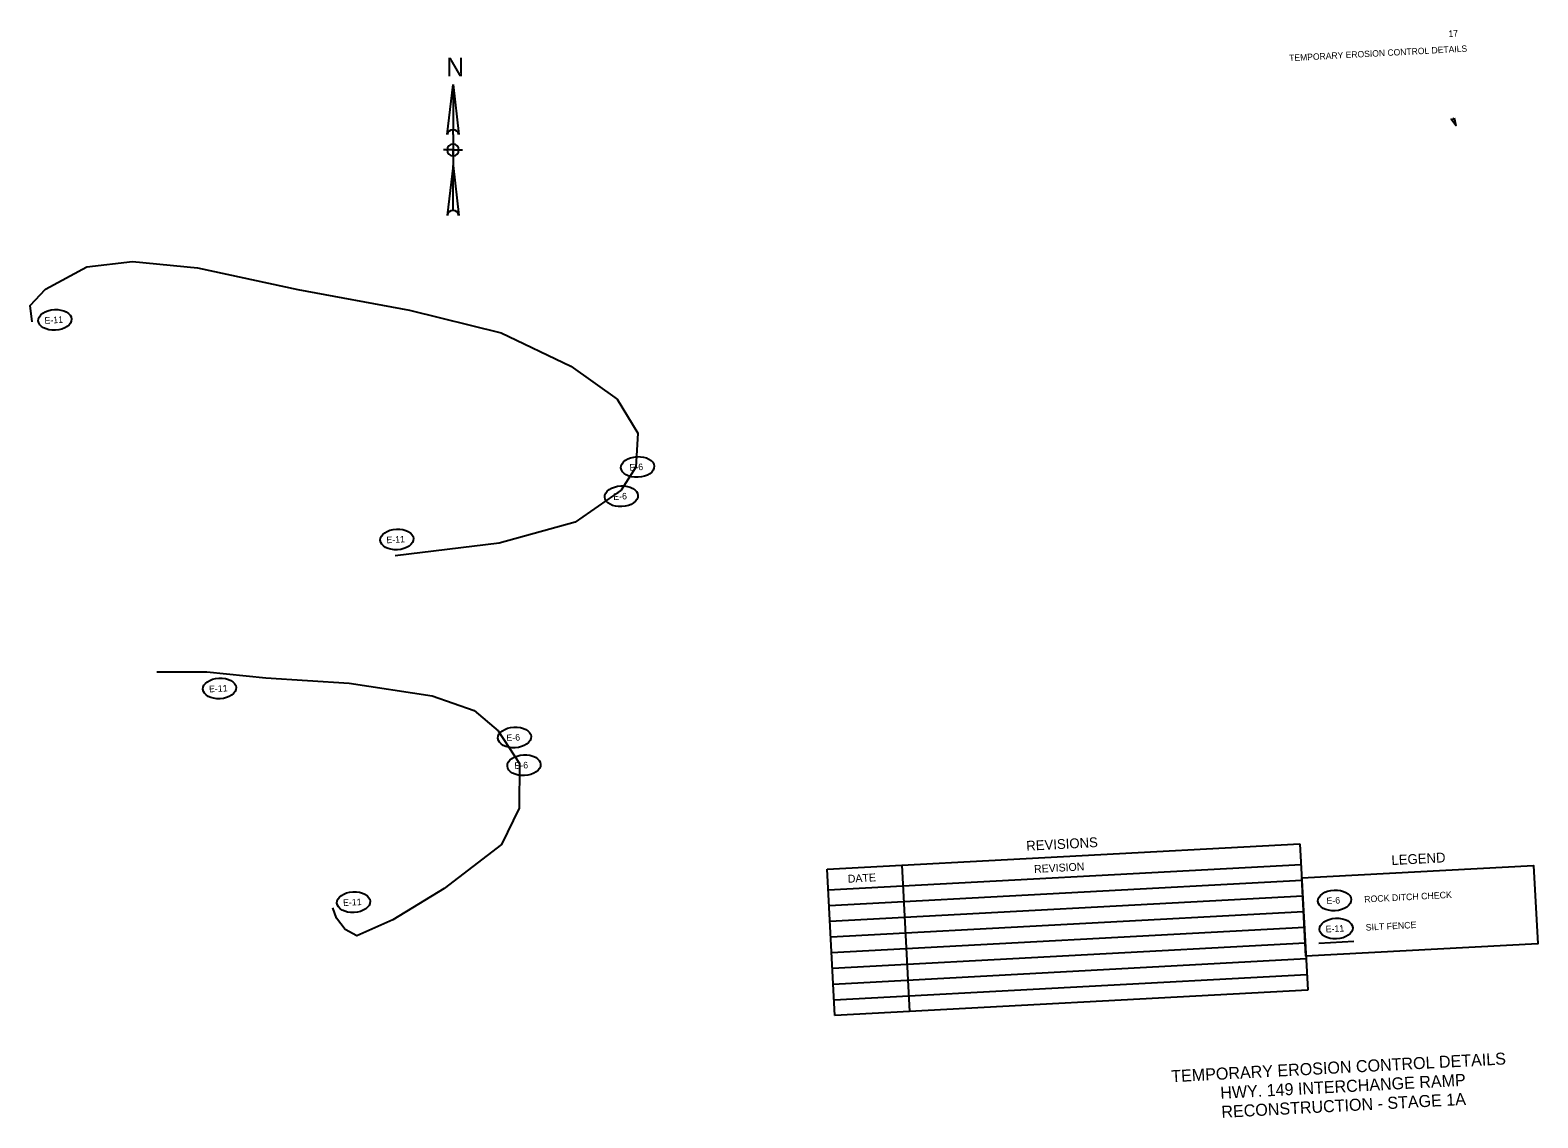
# Model space of a CAD drawing. Extents: x 251493 to 254667, y 216764 to 225410.
# Drawn here: x 251493 to 254251, y 223420 to 225410 of the extents above; entities that cross this region are included whole.
import ezdxf

# ---------------------------------------------------------------- set-up
doc = ezdxf.new("R2010")
doc.units = 0
for name, color, linetype in [('24X36', 7, 'Continuous'), ('Level 1', 7, 'Continuous'), ('Level 2', 7, 'Continuous'), ('Level 30', 7, 'Continuous'), ('Level 58', 7, 'Continuous')]:
    doc.layers.add(name, color=color, linetype=linetype)

msp = doc.modelspace()

# ---------------------------------------------------------------- linework, layer by layer
at = {"layer": '24X36'}
msp.add_line((253850.8, 223739.5), (253914.7, 223743), dxfattribs=at)
for points in [[(251496.9, 224876.5), (251493, 224906.2), (251521.2, 224936.4), (251596.8, 224977.5), (251680, 224986.8), (251799, 224975.2), (251982.9, 224936), (252187.1, 224897.9), (252354.4, 224856.6), (252482, 224795.3), (252566.6, 224735.2), (252604.6, 224672.7), (252600.8, 224610.3), (252574.3, 224568.2), (252490.2, 224509.9), (252351.1, 224471.3), (252161, 224448)], [(251725, 224235.7), (251815.9, 224235.7), (251924.2, 224224.8), (252076.6, 224215), (252228.5, 224192.1), (252305.3, 224165.1), (252349.2, 224128), (252388.3, 224067.9), (252387.8, 223986.5), (252355.5, 223920.2), (252250.4, 223839.2), (252156.6, 223782.2), (252090.6, 223752.9), (252069, 223764.3), (252053.6, 223785), (252046.6, 223803.8)]]:
    msp.add_lwpolyline(points, dxfattribs=at)
at = {"layer": 'Level 1'}
for p, q in [((252255.7, 225219.4), (252266.6, 225310.9)), ((252266.6, 225310.9), (252277.5, 225219.4)), ((252266.6, 225310.9), (252266.6, 225228.1)), ((252266.6, 225219.4), (252266.6, 225228.1)), ((252266.6, 225219.4), (252266.6, 225202)), ((252255.3, 225191.1), (252249.2, 225191.1)), ((252266.6, 225191.1), (252256.1, 225191.1)), ((252266.6, 225202), (252266.6, 225191.1)), ((252266.6, 225191.1), (252266.6, 225180.2)), ((252266.6, 225191.1), (252277.5, 225191.1)), ((252266.6, 225180.2), (252266.6, 225191.1)), ((252277.5, 225191.1), (252284.1, 225191.1)), ((252277.5, 225191.1), (252277.5, 225191.1)), ((252266.6, 225162.8), (252255.7, 225071.4)), ((252266.6, 225180.2), (252266.6, 225162.8)), ((252266.6, 225080.1), (252266.6, 225162.8)), ((252266.6, 225162.8), (252277.5, 225071.4)), ((252951.1, 223874.6), (253816.1, 223920.9)), ((253816.1, 223920.9), (253830.4, 223653.5)), ((252965.4, 223607.1), (252951.1, 223874.6)), ((252953.1, 223837.2), (253818.1, 223883.5)), ((253087.5, 223881.9), (253101.8, 223614.4)), ((252954.6, 223808.4), (253819.6, 223854.8)), ((252956.2, 223779.7), (253821.2, 223826)), ((252957.7, 223750.9), (253822.7, 223797.2)), ((252959.2, 223722.1), (253824.2, 223768.5)), ((252960.8, 223693.4), (253825.8, 223739.7)), ((252962.3, 223664.6), (253827.3, 223711)), ((252963.9, 223635.9), (253828.9, 223682.2)), ((253830.4, 223653.5), (252965.4, 223607.1)), ((253830.4, 223653.5), (253830.4, 223653.5))]:
    msp.add_line(p, q, dxfattribs=at)
msp.add_lwpolyline([(253819.4, 223859.1), (254243.6, 223881.8), (254251.3, 223738), (253827.1, 223715.3)], close=True, dxfattribs=at)
for centre, radius, start, end in [((252266.6, 225217), 11.2, 90, 167.3196), ((252266.6, 225217), 11.2, 12.6804, 90), ((252266.6, 225191.1), 10.9, 90, 180), ((252266.6, 225191.1), 10.9, 180, 270), ((252266.6, 225191.1), 10.9, 0, 90), ((252266.6, 225191.1), 10.9, 270, 0), ((252266.6, 225068.9), 11.2, 90, 167.3196), ((252266.6, 225068.9), 11.2, 12.6804, 90)]:
    msp.add_arc(centre, radius, start, end, dxfattribs=at)
at = {"layer": 'Level 30'}
for centre in [(251538.3, 224880.1), (252604.3, 224610.9), (252574.6, 224557.3), (252163.9, 224478.3), (251839.4, 224205.6), (252379.1, 224115.9), (252396.5, 224065.1), (253879.4, 223817.6), (252084.6, 223814.4), (253882.2, 223766.1)]:
    msp.add_ellipse(centre, major_axis=(30.4, 1.6), ratio=0.622507, dxfattribs=at)
at = {"layer": 'Level 58'}
msp.add_lwpolyline([(254097.9, 225250.1), (254101.1, 225235.7), (254092.5, 225247.6), (254096.2, 225246.7)], close=True, dxfattribs=at)

# ---------------------------------------------------------------- texts
at = {"layer": 'Level 1'}
for s, height, p in [('17', 11.72, (254088, 225397.9)), ('TEMPORARY EROSION CONTROL DETAILS', 11.7, (253796.7, 225353.6)), ('DATE', 14.4, (252989.2, 223849.9)), ('REVISION', 14.4, (253330, 223867.8))]:
    msp.add_text(s, height=height, rotation=3.0666, dxfattribs=at).set_placement(p)
msp.add_text('N', height=34.2, dxfattribs=at).set_placement((252254, 225325.9))
at = {"layer": 'Level 2'}
for s, p in [('TEMPORARY EROSION CONTROL DETAILS', (253581.2, 223484.7)), ('HWY. 149 INTERCHANGE RAMP', (253670.9, 223454.4)), ('RECONSTRUCTION - STAGE 1A', (253672.9, 223419.5))]:
    msp.add_text(s, height=22, rotation=3.0666, dxfattribs=at).set_placement(p)
at = {"layer": 'Level 30'}
for s, height, p in [('E-11', 12, (251519.5, 224873)), ('E-6', 12, (252589.8, 224604)), ('E-6', 12, (252560.1, 224550.4)), ('E-11', 12, (252145.1, 224471.2)), ('E-11', 12, (251820.6, 224198.4)), ('E-6', 12, (252364.6, 224109)), ('E-6', 12, (252379.3, 224058.1)), ('REVISIONS', 18, (253315.8, 223908.4)), ('LEGEND', 18, (253983.9, 223882.2)), ('E-11', 12, (252065.8, 223807.3)), ('E-6', 12, (253864.9, 223810.7)), ('ROCK DITCH CHECK', 11.997, (253933.9, 223813.7)), ('E-11', 12, (253863.4, 223759)), ('SILT FENCE ', 11.997, (253936.7, 223762.2))]:
    msp.add_text(s, height=height, rotation=3.0666, dxfattribs=at).set_placement(p)

doc.saveas('drawing.dxf')
